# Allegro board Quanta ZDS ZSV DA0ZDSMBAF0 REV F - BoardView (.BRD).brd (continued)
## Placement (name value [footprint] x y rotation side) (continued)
R10962  10k/f_2  [R0201]  198.88 13.57 0 bottom
R10963  *100k/f_2  [R0201]  201.42 17.25 0 bottom
R10964  *1m/f_2  [R0201]  203.07 13.32 270 bottom
R10965  *0_4/s  [S0402]  119.22 36.48 180 bottom
R10966  2.2k_2  [R0201]  98.8 42.81 0 top
R10967  2.2k_2  [R0201]  98.8 43.64 0 top
R10968  4.7k_2  [R0201]  103.96 41.69 180 top
R10969  *10k/f_2  [R0201]  107.84 52.68 90 top
R10970  10k/f_2  [R0201]  102.08 37.04 0 top
R10971  2.2k_2  [R0201]  105.3 52.74 90 top
R10972  10k/f_2  [R0201]  103.37 49 180 top
R10973  *8.2k/f_2  [R0201]  99.71 38.21 270 top
R10974  *10k/f_2  [R0201]  104.77 34.17 180 top
R10975  *10k/f_2  [R0201]  99.02 34.37 0 top
R10976  *0_2  [R0201]  191.84 36.68 0 bottom
R10978  *2.2k_4  [R0402]  228.09 15.98 0 bottom
R10979  *2.2k_4  [R0402]  228.09 14.97 0 bottom
R10980  *10k/f_4  [R0402]  224.91 26.02 90 bottom
R10981  *10k/f_4  [R0402]  223.89 26.02 90 bottom
R10982  100k/f_4  [R0402]  228.09 17 180 bottom
R10983  10k/f_4  [R0402]  228.09 18.02 180 bottom
R10985  1k/f_4  [R0402]  225.93 26.02 90 bottom
R10987  10k/f_4  [R0402]  215.77 21.7 90 bottom
R10988  100k/f_4  [R0402]  215.39 19.41 270 bottom
R10989  10k/f_4  [R0402]  237.26 27.11 180 bottom
R10990  4.7k_4  [R0402]  216.4 17.13 270 bottom
R10991  10k/f_4  [R0402]  216.4 19.41 270 bottom
R10994  *7.15k/f_4  [R0402]  229.61 20.43 90 bottom
R10995  *1k/f_4  [R0402]  228.09 20.05 180 bottom
R10996  *5.9k/f_4  [R0402]  223.26 27.92 270 bottom
R10997  *2.2k_4  [R0402]  222.88 26.02 90 bottom
R10998  *0_6/s  [S0603]  228.47 25.38 0 bottom
R10999  *1m/f_2  [R0201]  188.08 5.19 0 bottom
R11000  *100k/f_2  [R0201]  196.72 3.54 270 bottom
R11001  *1m_4  [R0402]  195.95 5.95 90 bottom
R11002  *100k/f_4  [R0402]  195.95 4.17 90 bottom
R11003  *0_4/s  [S0402]  202.18 4.68 0 bottom
R11004  93.1k/f_4  [R0402]  200.65 2.9 90 bottom
R11005  100k/f_4  [R0402]  192.53 2.52 0 bottom
R11006  52.3k/f_4  [R0402]  199.64 2.9 90 bottom
R11007  10k/f_2  [R0201]  194.94 3.16 180 bottom
R11008  2m_4  [R0402]  257.42 31.1 270 bottom
R11009  10k/f_2  [R0201]  194.94 3.92 0 bottom
R11016  *100k/f_2  [R0201]  194.94 4.68 180 bottom
R11019  2m_4  [R0402]  257.42 32.87 90 bottom
R11022  *0_6/s  [S0603]  207.13 5.7 180 bottom
R11023  *0_6/s  [S0603]  207.13 7.35 180 bottom
SPAD1  *spad-re275x126np  [SPAD-RE275X126NP]  115.89 59.9 0 top
SPAD2  spad-zds-1  [SPAD-ZDS-1]  205.5 58.24 0 top
SPAD3  *spad-re275x275np  [SPAD-RE275X275NP]  25.6 58 0 top
SPAD4  *spad-c138  [SPAD-C138]  40.67 27.65 0 top
SPAD7  *spad-c138  [SPAD-C138]  24.15 18.3 0 top
SPAD8  *spad-c138  [SPAD-C138]  257.15 17.6 0 top
SPAD9  *spad-re236x118np  [SPAD-RE236X118NP]  49.37 1.51 0 top
SPAD10  *spad-re236x118np  [SPAD-RE236X118NP]  144.39 1.51 0 top
SPAD11  spad-re173x114np  [SPAD-RE173X114NP]  269.9 26.5 0 top
SPAD12  *spad-c138  [SPAD-C138]  257.15 -0.9 0 top
SPAD13  *spad-re197x197np  [SPAD-RE197X197NP]  48.3 54.19 180 bottom
SPAD14  spad-c138  [SPAD-C138]  91.17 27.65 0 top
SPAD15  spad-c138  [SPAD-C138]  57.3 18.3 0 top
SPAD16  spad-c138  [SPAD-C138]  241.67 27.65 0 top
SPAD17  spad-c138  [SPAD-C138]  191.55 27.65 0 top
SPAD18  spad-c138  [SPAD-C138]  158.05 18.3 0 top
SPAD19  spad-c138  [SPAD-C138]  208.55 17.8 0 top
SPAD20  spad-c138  [SPAD-C138]  7.55 18.3 0 top
SPAD22  spad-re236x118np  [SPAD-RE236X118NP]  201.4 1.5 0 top
SW1  t3al-23s-q-t/r  [SW-T3AL-23-Q-TR-4P]  37.9 59.5 180 bottom
SW2  *bte-p-v-t/r  [SW-BTE-P-V-TR-4P]  36.49 27.16 90 bottom
SW3  *t3al-23s-q-t/r  [SW-T3AL-23-Q-TR-4P]  60.03 3.94 180 bottom
T1  *  [TP2650]  129.66 55.73 0 top
T2  *  [TP2650]  124.58 55.23 0 top
T3  *  [TP2650]  126.51 53.32 0 top
T4  *  [TP2650]  125.85 55.02 0 top
T5  *  [TP2650]  127.02 54.49 0 top
T6  *  [TP2650]  127.78 53.45 0 top
T7  *pad  [TP2650]  111.2 53.3 0 top
T8  *  [TP2650]  101.75 52.84 0 top
T9  *  [TP2650]  122.19 53.25 0 top
T10  *  [TP2650]  126.87 55.81 0 top
T11  *  [TP2650]  118.79 52.62 0 top
T12  *  [TP2650]  120.52 52.59 0 top
T13  *  [TP2650]  128.26 55.73 0 top
T14  *  [TP2650]  128.64 54.39 0 top
T15  *  [TP2650]  131.06 51.49 0 top
T16  *  [TP2650]  104.41 51.75 0 top
T17  *  [TP2650]  103.99 50.44 0 top
T18  *  [TP2650]  40.84 49.11 180 top
T19  *pad  [TP2650]  99.71 43.72 0 top
T20  *pad  [TP2650]  58.9 46.44 0 top
T21  *pad  [TP2650]  98.29 44.38 0 top
T22  *  [TP2650]  42.13 49.11 180 top
T23  *pad  [TP2650]  98.65 41.99 0 top
T24  *pad  [TP2650]  99.33 45.23 0 top
T25  *pad  [TP2650]  100.6 42.81 0 top
T28  *pad  [TP2650]  104.44 38.14 0 top
T29  *  [TP2650]  41.24 37.99 180 top
T30  *pad  [TP2650]  100.69 37.5 0 top
T32  *  [TP2650]  100.63 35.93 0 top
T33  *  [TP2650]  80.94 35.5 90 top
T34  *pad  [TP2050]  103.91 34.78 0 top
T35  *  [TP2050]  104.51 32.54 0 top
T39  *  [TP2650]  122.83 49.87 90 bottom
T40  *  [TP2650]  126.46 49.21 270 bottom
T41  *  [TP2650]  110.08 46.92 180 bottom
T42  *pad  [TP2650]  73.53 38.08 180 bottom
T43  *  [TP2650]  111.65 37.48 180 bottom
T44  *  [TP2650]  128.85 37.37 180 bottom
T45  *  [TP2650]  109.92 36.86 180 bottom
T46  *  [TP2650]  126.33 36.72 180 bottom
T49  *  [TP2650]  111.07 36.23 180 bottom
T50  *  [TP2650]  125.37 35.62 180 bottom
T51  *  [TP2650]  117.16 35.24 180 bottom
T52  *  [TP2650]  111.19 34.93 180 bottom
T53  *  [TP2650]  128.34 34.78 180 bottom
T54  *  [TP2650]  109.34 34.61 180 bottom
T56  *pad  [TP2650]  60.12 18.74 180 bottom
T60  *pad  [TP2650]  58.79 10.35 180 bottom
T62  *pad  [TP2050]  167 15.73 90 bottom
T63  *pad  [TP2050]  167.74 13.49 90 bottom
T64  *pad  [TP2050]  156.05 6.08 90 bottom
T65  *pad  [TP2050]  156.56 4.88 90 bottom
T68  *pad  [TP2650]  151.02 2.38 90 bottom
T69  *pad  [TP2650]  152.29 2.38 90 bottom
T70  *pad  [TP2050]  153.56 2.38 90 bottom
TP3  *  [TP2650]  244.19 11.59 0 bottom
TP6  *pad_nc  [TP2050]  226.56 23.98 180 bottom
TP23  *pad_nc  [TP2050]  218.1 19.57 180 bottom
TP24  *pad_nc  [TP2050]  218.56 23.6 180 bottom
TP25  *pad_nc  [TP2050]  218.43 16.62 180 bottom
TP26  *pad_nc  [TP2050]  222.62 15.98 180 bottom
TP27  *pad_nc  [TP2050]  230.04 23.1 180 bottom
TP28  *pad_nc  [TP2050]  222.88 13.29 180 bottom
TP29  *pad_nc  [TP2050]  223.79 15.48 180 bottom
TP30  *pad_nc  [TP2050]  223.77 14.21 180 bottom
TP31  *pad_nc  [TP2050]  226.64 16.11 180 bottom
TP32  *pad_nc  [TP2050]  226.64 14.71 180 bottom
TP38  *pad_nc  [TP2050]  229.61 17.76 180 bottom
TP39  *pad_nc  [TP2050]  230.24 19.03 180 bottom
TP88  *  [TP2050]  171.7 4.81 180 bottom
TP89  *  [TP2050]  171.67 8.08 180 bottom
U1  gd25b64csigr  [SOIC8-8-1_27]  45.63 46.28 90 top
U2  tc7sh08fu(f)  [SSOP5-P-A-TOSHIBA-B]  99.26 51.07 180 top
U3  skylake_ulx/bga  [BGA1515-INTEL-SKL_KBL-Y]  117.6 41.85 270 top
U4  mll@az1045-08f.r7g  [ESD-3_8X1-9P]  260.8 30.46 90 top
U4A1  lpddr3_ss_8gl  [BGA178-SAMSUNG-K4E8E304EE]  106.27 18.49 180 bottom
U5  14@lis3dhtr  [LGA16-3X3-5]  84.4 34.79 90 top
U5A1  lpddr3_ss_8gl  [BGA178-SAMSUNG-K4E8E304EE]  124.04 18.49 180 bottom
U6A1  lpddr3_ss_8gl  [BGA178-SAMSUNG-K4E8E304EE]  147 19.63 270 bottom
U7A1  lpddr3_ss_8gl  [BGA178-SAMSUNG-K4E8E304EE]  147 36.96 270 bottom
U8  mll@az1043-08f.r7g  [ESD-3_8X1-9P]  259.45 34.27 90 bottom
U9  tmp432adgsr  [TSSOP10-4_9-5]  85.65 27.08 90 bottom
U10  tps2592badrcr  [QFN10-3X3-5-16P]  199.64 21.19 180 bottom
U11  *tc7sh08fu(f)  [SSOP5-P-A-TOSHIBA-B]  200.4 15.35 180 bottom
U13  ps8743bqfn40gtr-b0  [QFN40-6X4-4-41P-0_8H]  251.38 22.9 180 bottom
U14  ptn36001  [QFN12-1_25X2_1-4]  233.8 24.87 270 bottom
U15  cbtl02043abq  [DHVQFN20-4_5X2_5-5-21P]  240.28 24.37 90 bottom
U16  ap21510fm-7  [DFN2018-6-1_8125X2_0125-5-7P]  220.97 14.46 270 bottom
U17  it8987vg/bx  [BGA128-ITE-IT8528VGAX]  51.89 10.91 270 bottom
U18  ap21510fm-7  [DFN2018-6-1_8125X2_0125-5-7P]  220.08 25.66 180 bottom
U19  alc255-cg  [QFN48-6X6-4-49P-ALC280]  247.95 8.47 0 bottom
U20  14@it8350g-128/cx-002c  [BGA64-ITE-IT8562VGCX]  152.06 6.29 90 bottom
U21  *g923-330t1uf  [SOT23-5]  236.65 3.72 180 bottom
U39  **poa@pi3usb102  [TQFN10-1_6X1_3-4-SMT]  172.84 6.43 180 bottom
U40  cypd4225-40lqxit  [QFN40-6X6-5-41P-0_6H]  222.37 20.3 180 bottom
U41  mll@az1043-08f.r7g  [ESD-3_8X1-9P]  259.84 28.56 270 bottom
U42  mll@az1045-08f.r7g  [ESD-3_8X1-9P]  261.87 30.84 90 bottom
U43  tps2592badrcr  [QFN10-3X3-5-16P]  198.88 6.2 90 bottom
U44  *tc7sh08fu(f)  [SSOP5-P-A-TOSHIBA-B]  193.03 4.68 90 bottom
Y1  24mhz_30  [XTL-3_2X2_5-2_2X1_7-0_8H]  99.69 48.09 0 top
Y2  32.768khz_20  [XTL-3_2X1_5-2_5-0_8H]  101.29 32.96 90 top

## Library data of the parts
BAT1 = 50277-01001-V01-10P-L
C1-C4 C12 C13 C44 C58 C69 C70 C73 C74 C77-C79 C82 C84 C85 C87-C89 C92-C95 C97-C110 C112 C113 C115-C120 C122-C129 C131-C133 C135-C144 C146-C148 C150-C159 C162-C174 C177-C184 C186 C188-C193 C195-C198 C200-C207 C210 C211 C213-C219 C221-C224 C226 C227 C229-C232 C234 C236-C246 C248-C258 C260 C261 C264 C266 C269-C276 C278 C279 C281 C283 C291 C310 C311 C324 C326 C330-C332 C334 C335 C352 C354 C356 C357 C374 C380 C388-C411 C413 C415-C417 C423 C424 C438 C440 C455 C456 C458 C461 C463 C464 C703 EC1-EC11 PC1-PC4 PC20 PC24 PC26-PC29 PC35 PC36 PC41 PC47 PC49-PC51 PC53 PC55 PC58-PC61 PC63 PC79 PC82-PC85 PC89-PC91 PC96-PC99 PC101 PC108 PC116-PC119 PC122 PC126 PC134-PC137 PC139 PC140 PC142-PC144 PC147 PC148 PC150 PC153 PC157 PC158 PC166 PC170 PC172 PC173 PC176 PC179 PC181-PC183 PC186 PC187 PC191 PC195-PC199 PC202 PC204 PC206 PC209 PC210 PC220 PC229 PC245 PC248-PC251 = C0201
C4A1-C4A5 C5 C5L1-C5L5 C6 C6A1-C6A9 C6L1-C6L9 C7 C7A1 C7A2 C7L1-C7L16 C9-C11 C14 C15 C19-C32 C41-C43 C45-C55 C57 C59-C68 C72 C75 C76 C86 C90 C91 C111 C114 C121 C130 C134 C145 C149 C160 C161 C175 C176 C185 C187 C194 C199 C209 C212 C225 C233 C235 C247 C259 C262 C263 C265 C267 C268 C277 C280 C282 C284-C290 C292-C305 C307-C309 C313-C318 C322 C323 C325 C327-C329 C333 C336-C351 C353 C355 C358 C359 C362 C364 C365 C367-C373 C375-C379 C381-C387 C412 C414 C418-C421 C428-C434 C436 C437 C439 C441-C447 C451-C454 C457 C459 C460 C462 C466-C468 C470-C473 C477-C482 C725 C726 C731 C927-C931 C941-C961 D1 D6-D13 D23 D28 D31 D49 D50 PC6 PC16 PC25 PC38-PC40 PC43 PC44 PC46 PC48 PC54 PC57 PC62 PC64 PC65 PC70 PC80 PC81 PC86-PC88 PC92-PC95 PC100 PC102 PC105-PC107 PC110-PC112 PC115 PC120 PC121 PC128 PC133 PC141 PC145 PC146 PC149 PC151 PC152 PC154-PC156 PC160-PC165 PC169 PC174 PC175 PC177 PC178 PC180 PC185 PC188 PC190 PC193 PC194 PC200 PC201 PC203 PC205 PC207 PC211 PC214 PC215 PC218 PC222 PC223 PC226-PC228 PC231-PC233 PC235 PC237-PC239 PC241-PC244 = C0402
C16-C18 C71 C80 C81 C83 C96 C228 C483-C491 C933 C962-C964 = C0805
C306 C312 C360 C425 C426 C934-C940 C965 PC5 PC7-PC15 PC17-PC19 PC21-PC23 PC30-PC34 PC37 PC42 PC45 PC52 PC56 PC66-PC69 PC71-PC78 PC109 PC113 PC114 PC123-PC125 PC127 PC129-PC132 PC138 PC159 PC167 PC168 PC171 PC184 PC189 PC192 PC208 PC212 PC213 PC216 PC217 PC219 PC221 PC224 PC225 PC230 PC234 PC236 PC240 PC255 PC256 = C0603
CL1_CL1 CL1_CL2 = FUNTP-C50-79-2P
CN1 = NGFF-NASE0-A6701-1S14-75P-KE
CN2 = NGFF-80149-3521-75P-KB
CN3 CN18 = UB31-DX07B024XJ1AR1000-24P-SMT
CN5 = AUDIO-AJ3F7D-Y150-412-6P
CN6 CN7 = 50376-00801-V01-8P-L
CN8 = 4251K-F06N-00L-6P-L
CN9 = 51569-03201-001-32P-L
CN10 = 50521-0060N-V01-6P-L
CN11 = 50699-02601-AT1-26P-L
CN12 = 50521-00641-V01-6P-L
CN13 CN14 = 50277-00201-001-2P-L
CN16 CN17 = 50521-00801-V01-8P-L
D2 L12 PR46 PR59 PR66 PR69 PR82 PR100 PR106 PR137 PR139 PR141 PR144 PR154 PR163 PR164 PR180-PR183 PR218 PR310 PR497 R284 R298 R311 R370 R380 R485 = R0603
D3 D18-D22 D35 D36 D39 PD3 PD6 PD7 = DSM
D4 D51 = D-1X0_6-D24V0L1B2LPS
D14-D17 EL1 L11 L14 L15 PR20 PR21 PR24 PR28 PR31 PR41 PR53 PR56 PR184-PR189 PR193 PR201 PR208 PR212 PR213 PR215 PR221 PR223 PR232 PR237 PR241 PR247 PR249 PR254 PR255 PR266 PR270 PR273 PR279 PR282-PR284 PR293 PR300 PR305-PR307 PR309 PR312-PR315 PR325 PR507 R4 R4L1 R4L2 R5L1 R5L2 R6L1-R6L3 R7A1 R39 R49 R53 R63 R81 R88 R89 R95 R115 R131 R139-R141 R149-R155 R157 R158 R170 R196-R198 R211 R219 R229 R249-R251 R254 R264 R274-R276 R282 R292 R299 R300 R308 R309 R313 R323 R325 R329 R341 R346 R351 R363-R365 R371 R372 R374 R378 R387 R389 R395-R397 R418 R425 R433 R434 R439 R444 R450 R472 R475 R477 R479 R481 R486 R490 R492-R497 R504 R675 R676 R10941 R10957 R10978-R10983 R10985 R10987-R10991 R10994-R10997 R11001 R11002 R11004-R11006 R11008 R11019 = R0402
D24-D27 D29 D30 D32-D34 D37 D38 = ESD-69X31
HOLE1 = H-TC276BC236D197P2
HOLE2 = H-TC315BC236D197P2
HOLE3 = H-C197D98P2BB
HOLE4 = H-O79X118D79X118N
HOLE5 HOLE9 = H-TC256BC177D177P2
HOLE6 = H-C79D79N
HOLE7 HOLE8 HOLE11 = H-TC217IBC197D98P2BB
HOLE10 = H-T99I-2BB
HOLE12 = H-T99I-1
HOLE13 HOLE14 = H-C51D51N
L13 PR280 = R0805
LED1-LED4 = LEDLTST-C190TGKT
LED5 LED6 = LEDLTST-S326KGJRKT-3P-SMT
MR1 = SOT23_123-2_8-1_9
PC103 PC104 = CC7343
PD1 = D-5_8X4_3-3P
PD2 PD4 PD9-PD13 = D-SOD523-1_2X0_8-1N4148WT-7
PD5 = D-DO-214AC
PL1 PL9 PL14 = CHOKE-PCMB041B-1R0MS
PL2 = L6_6X6_47-1_3
PL3 = L4_2X4_2
PL4 PL11 PL12 PL15 PR3 PR7 PR177 R226 R231 = S0805
PL5 = CHOKE-PCMB053T-1R0MS
PL6 PL7 = CHOKE-MPL73-1R5
PL8 PL10 PL13 = L3_2X2_5-1_55
PQ1-PQ5 PQ10 = POWER-3X3-65-10P
PQ6 PQ7 = POWER-5X6-1_27-7P
PQ8 PQ16 PQ19 PQ24 PQ27 PQ28 Q1-Q4 Q8 Q12-Q15 Q17 Q20-Q22 Q24 Q25 Q27-Q29 Q31 Q34 Q6062 Q6063 Q6068 Q6069 Q6071 = SOT23_213-3_3-2
PQ9 PQ23 PQ26 = SOT363-2_1-65-6P
PQ11 PQ12 PQ14 PQ17 PQ20 PQ21 = WDFN5-3_05X3_05-65
PQ15 PQ22 Q10 Q11 Q16 Q18 Q26 Q33 Q48 Q6064 Q6066 Q6067 Q6072 = SC70-2_1-65-6P
PR1 PR6 PR8 PR9 PR23 PR27 PR48 PR50-PR52 PR55 PR58 PR171 PR176 PR178 PR179 PR219 PR246 PR271 PR524 PR526 R171 R285 R296 R297 R310 R350 R355 R381 R393 R410 R417 R484 R10998 R11022 R11023 = S0603
PR2 PR4 PR5 PR12-PR19 PR33-PR38 PR43-PR45 PR47 PR54 PR57 PR60-PR63 PR65 PR70 PR71 PR73 PR75-PR77 PR86 PR87 PR89-PR91 PR93-PR98 PR102 PR103 PR109 PR110 PR113 PR114 PR116 PR123 PR126 PR127 PR132 PR134-PR136 PR138 PR143 PR146 PR147 PR149 PR151 PR155 PR161 PR166 PR168-PR170 PR172-PR174 PR190-PR192 PR198 PR203 PR210 PR222 PR224 PR230 PR231 PR234 PR239 PR244 PR250 PR258 PR259 PR261 PR262 PR264 PR285-PR287 PR290 PR291 PR294 PR298 PR299 PR301 PR302 PR304 PR308 PR330 PR492 PR493 PR502 PR525 R1 R5 R10 R16 R17 R31 R42 R43 R47 R96 R101 R106 R111 R116 R118 R120 R123 R142 R162 R165 R201 R207 R209 R212 R213 R224 R227 R255 R256 R259 R260 R295 R327 R335 R354 R382 R383 R404 R405 R408 R436 R441 R451 R460 R467 R487 R502 R505 R10946 R10947 R10960 = S0201
PR10 PR11 PR22 PR26 PR30 PR32 PR39 PR40 PR42 PR49 PR64 PR67 PR68 PR72 PR74 PR78-PR81 PR84 PR85 PR88 PR92 PR99 PR101 PR104 PR105 PR107 PR108 PR111 PR112 PR115 PR117-PR122 PR124 PR125 PR128-PR131 PR133 PR140 PR142 PR148 PR150 PR152 PR153 PR156-PR160 PR162 PR165 PR167 PR175 PR194 PR195 PR197 PR199 PR200 PR202 PR204-PR207 PR209 PR214 PR216 PR217 PR220 PR225-PR229 PR233 PR236 PR238 PR240 PR243 PR245 PR248 PR251-PR253 PR257 PR263 PR265 PR267-PR269 PR272 PR274-PR278 PR281 PR288 PR292 PR295-PR297 PR303 PR316-PR321 PR324 PR326 PR328 PR331 PR332 PR334 PR335 PR337 PR340-PR342 PR491 PR494-PR496 PR498-PR501 PR503-PR506 PR508-PR510 PR512-PR514 PR516-PR521 PR523 R2 R6-R9 R11-R15 R18-R30 R32-R38 R40 R41 R45 R46 R48 R50-R52 R54-R62 R64-R71 R73-R78 R80 R82-R84 R86 R87 R90-R94 R97-R100 R102 R103 R105 R107-R110 R112-R114 R117 R119 R121 R122 R124-R130 R133 R135 R136 R143 R144 R156 R161 R163 R164 R166-R169 R172-R180 R183 R184 R186-R195 R199 R200 R202-R206 R208 R214 R216-R218 R222 R223 R228 R230 R232 R236 R238 R241-R245 R247 R252 R253 R257 R258 R262 R263 R265 R266 R269 R273 R279-R281 R290 R291 R301-R306 R314 R318-R321 R324 R326 R330-R334 R336-R339 R342 R344 R345 R347 R352 R353 R356-R362 R366-R368 R373 R377 R384 R386 R390 R391 R399 R409 R411-R414 R416 R420-R422 R426 R427 R429 R430 R432 R435 R442 R443 R445-R447 R452 R455-R457 R459 R461 R462 R466 R473 R478 R482 R483 R488 R489 R499-R501 R503 R514 R543 R659 R668 R677 R860 R1526-R1534 R10930-R10932 R10934 R10942-R10944 R10948-R10956 R10959 R10961-R10964 R10966-R10976 R10999 R11000 R11007 R11009 R11016 = R0201
PR25 PR29 PR83 PR145 PR196 PR211 PR235 PR242 PR256 PR311 PR327 PR515 PR522 R3 R104 R145 R146 R160 R220 R240 R283 R307 R379 R392 R402 R423 R448 R474 R10965 R11003 = S0402
PR260 PR289 = F3_2X1_65-2_8
PU1 PU3 PU6 PU9 PU13 PU22 = SON14-3X2-4-15P-SMT
PU2 = DFN8-2X2-5-9P-NCP5901
PU4 = SOT23-5-2_8-95-5P-G708
PU5 = BGA168-TEXAS-TPS650830ZAJT
PU7 PU11 = QFN13-2X3-5
PU8 PU10 PU18-PU20 = SOT353-1-2_125-65-5P
PU12 = QFN52-6X6-4-53P-1H
PU14 = QFN28-4X4-4-38P
PU15 = TDFN10-3X3-5-11P-APL5620QBI-TRG
PU16 PU17 PU21 = SOT23-5-2_8-95-5P-1_3H
Q19 Q6070 = PG-TSDSON-8-8P-R
Q23 Q30 = UMT_213-3-1_3
SPAD1 = SPAD-RE275X126NP
SPAD2 = SPAD-ZDS-1
SPAD3 = SPAD-RE275X275NP
SPAD4 SPAD7 SPAD8 SPAD12 SPAD14-SPAD20 = SPAD-C138
SPAD9 SPAD10 SPAD22 = SPAD-RE236X118NP
SPAD11 = SPAD-RE173X114NP
SPAD13 = SPAD-RE197X197NP
SW1 SW3 = SW-T3AL-23-Q-TR-4P
SW2 = SW-BTE-P-V-TR-4P
T1-T25 T28-T30 T32 T33 T39-T46 T49-T54 T56 T60 T68 T69 TP3 = TP2650
T34 T35 T62-T65 T70 TP6 TP23-TP32 TP38 TP39 TP88 TP89 = TP2050
U1 = SOIC8-8-1_27
U2 U11 U44 = SSOP5-P-A-TOSHIBA-B
U3 = BGA1515-INTEL-SKL_KBL-Y
U4 U8 U41 U42 = ESD-3_8X1-9P
U4A1 U5A1 U6A1 U7A1 = BGA178-SAMSUNG-K4E8E304EE
U5 = LGA16-3X3-5
U9 = TSSOP10-4_9-5
U10 U43 = QFN10-3X3-5-16P
U13 = QFN40-6X4-4-41P-0_8H
U14 = QFN12-1_25X2_1-4
U15 = DHVQFN20-4_5X2_5-5-21P
U16 U18 = DFN2018-6-1_8125X2_0125-5-7P
U17 = BGA128-ITE-IT8528VGAX
U19 = QFN48-6X6-4-49P-ALC280
U20 = BGA64-ITE-IT8562VGCX
U21 = SOT23-5
U39 = TQFN10-1_6X1_3-4-SMT
U40 = QFN40-6X6-5-41P-0_6H
Y1 = XTL-3_2X2_5-2_2X1_7-0_8H
Y2 = XTL-3_2X1_5-2_5-0_8H

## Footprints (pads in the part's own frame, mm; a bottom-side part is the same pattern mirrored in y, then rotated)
4251K-F06N-00L-6P-L
  rect 0.406x0.61 smd: 1(-1.5,1.375) 2(-0.9,1.375) 3(-0.3,1.375) 4(0.3,1.375) 5(0.9,1.375) 6(1.5,1.375)
  rect 0.711x1.041 smd: 7(-2.45,0) 8(2.45,0)
50277-00201-001-2P-L
  rect 0.787x1.905 smd: 1(-0.625,4.925) 2(0.625,4.925)
  rect 1.295x3.353 smd: 3(-3.475,0) 4(3.475,0)
50277-01001-V01-10P-L
  rect 0.787x1.905 smd: 1(-5.625,4.925) 2(-4.375,4.925) 3(-3.125,4.925) 4(-1.875,4.925) 5(-0.625,4.925) 6(0.625,4.925) 7(1.875,4.925) 8(3.125,4.925) 9(4.375,4.925) 10(5.625,4.925)
  rect 1.295x3.353 smd: 11(-8.475,0) 12(8.475,0)
50376-00801-V01-8P-L
  rect 0.406x0.61 smd: 1(-2.1,1.375) 2(-1.5,1.375) 3(-0.9,1.375) 4(-0.3,1.375) 5(0.3,1.375) 6(0.9,1.375) 7(1.5,1.375) 8(2.1,1.375)
  rect 0.711x1.041 smd: 9(-3.05,0) 10(3.05,0)
50521-0060N-V01-6P-L
  rect 0.305x0.787 smd: 1(-1.25,2.5) 2(-0.75,2.5) 3(-0.25,2.5) 4(0.25,2.5) 5(0.75,2.5) 6(1.25,2.5)
  rect 0.406x0.787 smd: 7(-2.25,0) 8(2.25,0)
50521-00641-V01-6P-L
  rect 0.305x0.787 smd: 1(-1.25,2.5) 2(-0.75,2.5) 3(-0.25,2.5) 4(0.25,2.5) 5(0.75,2.5) 6(1.25,2.5)
  rect 0.406x0.787 smd: 7(-2.25,0) 8(2.25,0)
50521-00801-V01-8P-L
  rect 0.305x0.787 smd: 1(-1.75,2.5) 2(-1.25,2.5) 3(-0.75,2.5) 4(-0.25,2.5) 5(0.25,2.5) 6(0.75,2.5) 7(1.25,2.5) 8(1.75,2.5)
  rect 0.406x0.787 smd: 9(-2.75,0) 10(2.75,0)
50699-02601-AT1-26P-L
  rect 0.229x0.787 smd: 1(-10,3.3) 2(-9.2,3.3) 3(-8.4,3.3) 4(-7.6,3.3) 5(-6.8,3.3) 6(-6,3.3) 7(-5.2,3.3) 8(-4.4,3.3) 9(-3.6,3.3) 10(-2.8,3.3) 11(-2,3.3) 12(-1.2,3.3) 13(-0.4,3.3) 14(0.4,3.3) 15(1.2,3.3) 16(2,3.3) 17(2.8,3.3) 18(3.6,3.3) 19(4.4,3.3) 20(5.2,3.3) 21(6,3.3) 22(6.8,3.3) 23(7.6,3.3) 24(8.4,3.3) 25(9.2,3.3) 26(10,3.3)
  rect 0.559x1.295 smd: 27(-11.625,0) 28(11.625,0)
51569-03201-001-32P-L
  round 0.787 hole 0.787 unplated: (-8.8,0) (8.8,0)
  rect 0.305x0.889 smd: 1(-7.75,3.85) 2(-7.25,3.85) 3(-6.75,3.85) 4(-6.25,3.85) 5(-5.75,3.85) 6(-5.25,3.85) 7(-4.75,3.85) 8(-4.25,3.85) 9(-3.75,3.85) 10(-3.25,3.85) 11(-2.75,3.85) 12(-2.25,3.85) 13(-1.75,3.85) 14(-1.25,3.85) 15(-0.75,3.85) 16(-0.25,3.85) 17(0.25,3.85) 18(0.75,3.85) 19(1.25,3.85) 20(1.75,3.85) 21(2.25,3.85) 22(2.75,3.85) 23(3.25,3.85) 24(3.75,3.85) 25(4.25,3.85) 26(4.75,3.85) 27(5.25,3.85) 28(5.75,3.85) 29(6.25,3.85) 30(6.75,3.85) 31(7.25,3.85) 32(7.75,3.85)
  rect 1.499x1.499 smd: 33(-10.25,-0.3) 34(10.25,-0.3)
AUDIO-AJ3F7D-Y150-412-6P
  rect 1.245x2.007 hole 0.508x1.397: 1(-4.35,-3) 2(-4.35,0.05) 3(-4.35,5.7) 4(4.35,5.7) 5(4.35,0.05) 6(4.35,-3)
BGA64-ITE-IT8562VGCX
  round 0.254 smd: A1(-2,2) A2(-1.5,2) A3(-1,2) A4(-0.5,2) A5(0,2) A6(0.5,2) A7(1,2) A8(1.5,2) A9(2,2) B1(-2,1.5) B9(2,1.5) C1(-2,1) C9(2,1) D1(-2,0.5) D9(2,0.5) E1(-2,0) E9(2,0) F1(-2,-0.5) F9(2,-0.5) G1(-2,-1) G9(2,-1) H1(-2,-1.5) H9(2,-1.5) J1(-2,-2) J2(-1.5,-2) J3(-1,-2) J4(-0.5,-2) J5(0,-2) J6(0.5,-2) J7(1,-2) J8(1.5,-2) J9(2,-2)
  round 0.279 smd: B2(-1.5,1.5) B3(-1,1.5) B4(-0.5,1.5) B5(0,1.5) B6(0.5,1.5) B7(1,1.5) B8(1.5,1.5) C2(-1.5,1) C8(1.5,1) D2(-1.5,0.5) D4(-0.5,0.5) D5(0,0.5) D6(0.5,0.5) D8(1.5,0.5) E2(-1.5,0) E4(-0.5,0) E6(0.5,0) E8(1.5,0) F2(-1.5,-0.5) F4(-0.5,-0.5) F5(0,-0.5) F6(0.5,-0.5) F8(1.5,-0.5) G2(-1.5,-1) G8(1.5,-1) H2(-1.5,-1.5) H3(-1,-1.5) H4(-0.5,-1.5) H5(0,-1.5) H6(0.5,-1.5) H7(1,-1.5) H8(1.5,-1.5)
BGA128-ITE-IT8528VGAX
  round 0.254 smd: A1(-3,-3) A2(-3,-2.5) A3(-3,-2) A4(-3,-1.5) A5(-3,-1) A6(-3,-0.5) A7(-3,0) A8(-3,0.5) A9(-3,1) A10(-3,1.5) A11(-3,2) A12(-3,2.5) A13(-3,3) B1(-2.5,-3) B2(-2.5,-2.5) B3(-2.5,-2) B4(-2.5,-1.5) B5(-2.5,-1) B6(-2.5,-0.5) B7(-2.5,0) B8(-2.5,0.5) B9(-2.5,1) B10(-2.5,1.5) B11(-2.5,2) B12(-2.5,2.5) B13(-2.5,3) C1(-2,-3) C2(-2,-2.5) C12(-2,2.5) C13(-2,3) D1(-1.5,-3) D2(-1.5,-2.5) D4(-1.5,-1.5) D5(-1.5,-1) D6(-1.5,-0.5) D7(-1.5,0) D8(-1.5,0.5) D9(-1.5,1) D10(-1.5,1.5) D12(-1.5,2.5) D13(-1.5,3) E1(-1,-3) E2(-1,-2.5) E4(-1,-1.5) E5(-1,-1) E6(-1,-0.5) E7(-1,0) E8(-1,0.5) E9(-1,1) E10(-1,1.5) E12(-1,2.5) E13(-1,3) F1(-0.5,-3) F2(-0.5,-2.5) F4(-0.5,-1.5) F5(-0.5,-1) F9(-0.5,1) F10(-0.5,1.5) F12(-0.5,2.5) F13(-0.5,3) G1(0,-3) G2(0,-2.5) G4(0,-1.5) G5(0,-1) G9(0,1) G10(0,1.5) G12(0,2.5) G13(0,3) H1(0.5,-3) H2(0.5,-2.5) H4(0.5,-1.5) H5(0.5,-1) H9(0.5,1) H10(0.5,1.5) H12(0.5,2.5) H13(0.5,3) J1(1,-3) J2(1,-2.5) J4(1,-1.5) J5(1,-1) J6(1,-0.5) J7(1,0) J8(1,0.5) J9(1,1) J10(1,1.5) J12(1,2.5) J13(1,3) K1(1.5,-3) K2(1.5,-2.5) K4(1.5,-1.5) K5(1.5,-1) K6(1.5,-0.5) K7(1.5,0) K8(1.5,0.5) K9(1.5,1) K10(1.5,1.5) K12(1.5,2.5) K13(1.5,3) L1(2,-3) L2(2,-2.5) L12(2,2.5) L13(2,3) M1(2.5,-3) M2(2.5,-2.5) M3(2.5,-2) M4(2.5,-1.5) M5(2.5,-1) M6(2.5,-0.5) M7(2.5,0) M8(2.5,0.5) M9(2.5,1) M10(2.5,1.5) M11(2.5,2) M12(2.5,2.5) M13(2.5,3) N1(3,-3) N2(3,-2.5) N3(3,-2) N4(3,-1.5) N5(3,-1) N6(3,-0.5) N7(3,0) N8(3,0.5) N9(3,1) N10(3,1.5) N11(3,2) N12(3,2.5) N13(3,3)
BGA168-TEXAS-TPS650830ZAJT
  round 0.254 smd: A1(-3,-3) A2(-3,-2.5) A3(-3,-2) A4(-3,-1.5) A5(-3,-1) A6(-3,-0.5) A7(-3,0) A8(-3,0.5) A9(-3,1) A10(-3,1.5) A11(-3,2) A12(-3,2.5) A13(-3,3) B1(-2.5,-3) B3(-2.5,-2) B4(-2.5,-1.5) B5(-2.5,-1) B6(-2.5,-0.5) B7(-2.5,0) B8(-2.5,0.5) B9(-2.5,1) B10(-2.5,1.5) B11(-2.5,2) B12(-2.5,2.5) B13(-2.5,3) C1(-2,-3) C2(-2,-2.5) C3(-2,-2) C4(-2,-1.5) C5(-2,-1) C6(-2,-0.5) C7(-2,0) C8(-2,0.5) C9(-2,1) C10(-2,1.5) C11(-2,2) C12(-2,2.5) C13(-2,3) D1(-1.5,-3) D2(-1.5,-2.5) D3(-1.5,-2) D4(-1.5,-1.5) D5(-1.5,-1) D6(-1.5,-0.5) D7(-1.5,0) D8(-1.5,0.5) D9(-1.5,1) D10(-1.5,1.5) D11(-1.5,2) D12(-1.5,2.5) D13(-1.5,3) E1(-1,-3) E2(-1,-2.5) E3(-1,-2) E4(-1,-1.5) E5(-1,-1) E6(-1,-0.5) E7(-1,0) E8(-1,0.5) E9(-1,1) E10(-1,1.5) E11(-1,2) E12(-1,2.5) E13(-1,3) F1(-0.5,-3) F2(-0.5,-2.5) F3(-0.5,-2) F4(-0.5,-1.5) F5(-0.5,-1) F6(-0.5,-0.5) F7(-0.5,0) F8(-0.5,0.5) F9(-0.5,1) F10(-0.5,1.5) F11(-0.5,2) F12(-0.5,2.5) F13(-0.5,3) G1(0,-3) G2(0,-2.5) G3(0,-2) G4(0,-1.5) G5(0,-1) G6(0,-0.5) G7(0,0) G8(0,0.5) G9(0,1) G10(0,1.5) G11(0,2) G12(0,2.5) G13(0,3) H1(0.5,-3) H2(0.5,-2.5) H3(0.5,-2) H4(0.5,-1.5) H5(0.5,-1) H6(0.5,-0.5) H7(0.5,0) H8(0.5,0.5) H9(0.5,1) H10(0.5,1.5) H11(0.5,2) H12(0.5,2.5) H13(0.5,3) J1(1,-3) J2(1,-2.5) J3(1,-2) J4(1,-1.5) J5(1,-1) J6(1,-0.5) J7(1,0) J8(1,0.5) J9(1,1) J10(1,1.5) J11(1,2) J12(1,2.5) J13(1,3) K1(1.5,-3) K2(1.5,-2.5) K3(1.5,-2) K4(1.5,-1.5) K5(1.5,-1) K6(1.5,-0.5) K7(1.5,0) K8(1.5,0.5) K9(1.5,1) K10(1.5,1.5) K11(1.5,2) K12(1.5,2.5) K13(1.5,3) L1(2,-3) L2(2,-2.5) L3(2,-2) L4(2,-1.5) L5(2,-1) L6(2,-0.5) L7(2,0) L8(2,0.5) L9(2,1) L10(2,1.5) L11(2,2) L12(2,2.5) L13(2,3) M1(2.5,-3) M2(2.5,-2.5) M3(2.5,-2) M4(2.5,-1.5) M5(2.5,-1) M6(2.5,-0.5) M7(2.5,0) M8(2.5,0.5) M9(2.5,1) M10(2.5,1.5) M11(2.5,2) M12(2.5,2.5) M13(2.5,3) N1(3,-3) N2(3,-2.5) N3(3,-2) N4(3,-1.5) N5(3,-1) N6(3,-0.5) N7(3,0) N8(3,0.5) N9(3,1) N10(3,1.5) N11(3,2) N12(3,2.5) N13(3,3)
BGA178-SAMSUNG-K4E8E304EE
  round 0.254 smd: A1(-5.2,-4.8) A2(-5.2,-4) A3(-5.2,-3.2) A4(-5.2,-2.4) A5(-5.2,-1.6) A6(-5.2,-0.8) A8(-5.2,0.8) A9(-5.2,1.6) A10(-5.2,2.4) A11(-5.2,3.2) A12(-5.2,4) A13(-5.2,4.8) B1(-4.55,-4.8) B2(-4.55,-4) B3(-4.55,-3.2) B4(-4.55,-2.4) B5(-4.55,-1.6) B6(-4.55,-0.8) B8(-4.55,0.8) B9(-4.55,1.6) B10(-4.55,2.4) B11(-4.55,3.2) B12(-4.55,4) B13(-4.55,4.8) C2(-3.9,-4) C3(-3.9,-3.2) C4(-3.9,-2.4) C5(-3.9,-1.6) C6(-3.9,-0.8) C8(-3.9,0.8) C9(-3.9,1.6) C10(-3.9,2.4) C11(-3.9,3.2) C12(-3.9,4) D2(-3.25,-4) D3(-3.25,-3.2) D4(-3.25,-2.4) D5(-3.25,-1.6) D6(-3.25,-0.8) D8(-3.25,0.8) D9(-3.25,1.6) D10(-3.25,2.4) D11(-3.25,3.2) D12(-3.25,4) E2(-2.6,-4) E3(-2.6,-3.2) E4(-2.6,-2.4) E5(-2.6,-1.6) E6(-2.6,-0.8) E8(-2.6,0.8) E9(-2.6,1.6) E10(-2.6,2.4) E11(-2.6,3.2) E12(-2.6,4) F2(-1.95,-4) F3(-1.95,-3.2) F4(-1.95,-2.4) F5(-1.95,-1.6) F6(-1.95,-0.8) F8(-1.95,0.8) F9(-1.95,1.6) F10(-1.95,2.4) F11(-1.95,3.2) F12(-1.95,4) G2(-1.3,-4) G3(-1.3,-3.2) G4(-1.3,-2.4) G5(-1.3,-1.6) G6(-1.3,-0.8) G8(-1.3,0.8) G9(-1.3,1.6) G10(-1.3,2.4) G11(-1.3,3.2) G12(-1.3,4) H2(-0.65,-4) H3(-0.65,-3.2) H4(-0.65,-2.4) H5(-0.65,-1.6) H6(-0.65,-0.8) H8(-0.65,0.8) H9(-0.65,1.6) H10(-0.65,2.4) H11(-0.65,3.2) H12(-0.65,4) J2(0,-4) J3(0,-3.2) J4(0,-2.4) J5(0,-1.6) J6(0,-0.8) J8(0,0.8) J9(0,1.6) J10(0,2.4) J11(0,3.2) J12(0,4) K2(0.65,-4) K3(0.65,-3.2) K4(0.65,-2.4) K5(0.65,-1.6) K6(0.65,-0.8) K8(0.65,0.8) K9(0.65,1.6) K10(0.65,2.4) K11(0.65,3.2) K12(0.65,4) L2(1.3,-4) L3(1.3,-3.2) L4(1.3,-2.4) L5(1.3,-1.6) L6(1.3,-0.8) L8(1.3,0.8) L9(1.3,1.6) L10(1.3,2.4) L11(1.3,3.2) L12(1.3,4) M2(1.95,-4) M3(1.95,-3.2) M4(1.95,-2.4) M5(1.95,-1.6) M6(1.95,-0.8) M8(1.95,0.8) M9(1.95,1.6) M10(1.95,2.4) M11(1.95,3.2) M12(1.95,4) N2(2.6,-4) N3(2.6,-3.2) N4(2.6,-2.4) N5(2.6,-1.6) N6(2.6,-0.8) N8(2.6,0.8) N9(2.6,1.6) N10(2.6,2.4) N11(2.6,3.2) N12(2.6,4) P2(3.25,-4) P3(3.25,-3.2) P4(3.25,-2.4) P5(3.25,-1.6) P6(3.25,-0.8) P8(3.25,0.8) P9(3.25,1.6) P10(3.25,2.4) P11(3.25,3.2) P12(3.25,4) R2(3.9,-4) R3(3.9,-3.2) R4(3.9,-2.4) R5(3.9,-1.6) R6(3.9,-0.8) R8(3.9,0.8) R9(3.9,1.6) R10(3.9,2.4) R11(3.9,3.2) R12(3.9,4) T1(4.55,-4.8) T2(4.55,-4) T3(4.55,-3.2) T4(4.55,-2.4) T5(4.55,-1.6) T6(4.55,-0.8) T8(4.55,0.8) T9(4.55,1.6) T10(4.55,2.4) T11(4.55,3.2) T12(4.55,4) T13(4.55,4.8) U1(5.2,-4.8) U2(5.2,-4) U3(5.2,-3.2) U4(5.2,-2.4) U5(5.2,-1.6) U6(5.2,-0.8) U8(5.2,0.8) U9(5.2,1.6) U10(5.2,2.4) U11(5.2,3.2) U12(5.2,4) U13(5.2,4.8)
BGA1515-INTEL-SKL_KBL-Y
  round 0.25 smd: A5(-7.541,-8.401) A7(-7.541,-7.946) A9(-7.541,-7.407) A11(-7.541,-6.763) A14(-7.541,-6.119) A16(-7.541,-5.475) A18(-7.541,-4.831) A20(-7.541,-4.187) A22(-7.541,-3.543) A24(-7.541,-2.898) A26(-7.541,-2.254) A28(-7.541,-1.61) A30(-7.541,-0.966) A32(-7.541,-0.322) A34(-7.541,0.322) A36(-7.541,0.966) A38(-7.541,1.61) A40(-7.541,2.255) A42(-7.541,2.899) A44(-7.541,3.543) A46(-7.541,4.187) A48(-7.541,4.831) A50(-7.541,5.475) A52(-7.541,6.119) A54(-7.541,6.764) A56(-7.541,7.408) A58(-7.541,7.953) A60(-7.541,8.401) A62(-7.541,8.856) A64(-7.541,9.31) AA2(-1.932,-9.038) AA4(-1.932,-8.546) AA6(-1.932,-8.053) AA8(-1.932,-7.56) AA10(-1.932,-7.067) AA12(-1.932,-6.575) AA53(-1.932,6.575) AA55(-1.932,7.068) AA57(-1.932,7.56) AB1(-1.61,-9.31) AB3(-1.61,-8.792) AB5(-1.61,-8.299) AB7(-1.61,-7.806) AB9(-1.61,-7.314) AB11(-1.61,-6.821) AB13(-1.605,-6.328) AB54(-1.61,6.821) AB56(-1.61,7.314) AB58(-1.61,7.807) AB64(-1.61,9.31) AC2(-1.288,-9.038) AC4(-1.288,-8.546) AC6(-1.288,-8.053) AC8(-1.288,-7.56) AC10(-1.288,-7.067) AC12(-1.288,-6.575) AC53(-1.288,6.575) AC55(-1.288,7.068) AC57(-1.288,7.56) AD1(-0.966,-9.31) AD3(-0.966,-8.792) AD5(-0.966,-8.299) AD7(-0.966,-7.806) AD9(-0.966,-7.314) AD11(-0.966,-6.821) AD13(-0.961,-6.328) AD54(-0.966,6.821) AD56(-0.966,7.314) AD58(-0.966,7.807) AD64(-0.966,9.31) AE2(-0.644,-9.038) AE4(-0.644,-8.546) AE6(-0.644,-8.053) AE8(-0.644,-7.56) AE10(-0.644,-7.067) AE12(-0.644,-6.575) AE53(-0.644,6.575) AE55(-0.644,7.068) AE57(-0.644,7.56) AF1(-0.322,-9.31) AF3(-0.322,-8.792) AF5(-0.322,-8.299) AF7(-0.322,-7.806) AF9(-0.322,-7.314) AF11(-0.322,-6.821) AF13(-0.317,-6.328) AF54(-0.322,6.821) AF56(-0.322,7.314) AF58(-0.322,7.807) AF60(-0.322,8.299) AF62(-0.322,8.792) AF64(-0.322,9.31) AG2(0,-9.038) AG4(0,-8.546) AG6(0,-8.053) AG8(0,-7.56) AG10(0,-7.067) AG12(0,-6.575) AG53(0,6.575) AG55(0,7.068) AG57(0,7.56) AG59(0,8.053) AG61(0,8.546) AG63(0,9.039) AH1(0.322,-9.31) AH3(0.322,-8.792) AH5(0.322,-8.299) AH7(0.322,-7.806) AH9(0.322,-7.314) AH11(0.322,-6.821) AH13(0.327,-6.328) AH54(0.322,6.821) AH56(0.322,7.314) AH58(0.322,7.807) AH60(0.322,8.299) AH62(0.322,8.792) AH64(0.322,9.31) AJ2(0.644,-9.038) AJ4(0.644,-8.546) AJ6(0.644,-8.053) AJ8(0.644,-7.56) AJ10(0.644,-7.067) AJ12(0.644,-6.575) AJ53(0.644,6.575) AJ55(0.644,7.068) AJ57(0.644,7.56) AJ59(0.644,8.053) AJ61(0.644,8.546) AJ63(0.644,9.039) AK1(0.966,-9.31) AK3(0.966,-8.792) AK5(0.966,-8.299) AK7(0.966,-7.806) AK9(0.966,-7.314) AK11(0.966,-6.821) AK13(0.971,-6.328) AK54(0.966,6.821) AK56(0.966,7.314) AK58(0.966,7.807) AK60(0.966,8.299) AK62(0.966,8.792) AK64(0.966,9.31) AL2(1.288,-9.038) AL4(1.288,-8.546) AL6(1.288,-8.053) AL8(1.288,-7.56) AL10(1.288,-7.067) AL12(1.288,-6.575) AL53(1.288,6.575) AL55(1.288,7.068) AL57(1.288,7.56) AL59(1.288,8.053) AL61(1.288,8.546) AL63(1.288,9.039) AM1(1.61,-9.31) AM3(1.61,-8.792) AM5(1.61,-8.299) AM7(1.61,-7.806) AM9(1.61,-7.314) AM11(1.61,-6.821) AM13(1.615,-6.328) AM54(1.61,6.821) AM56(1.61,7.314) AM58(1.61,7.807) AM60(1.61,8.299) AM62(1.61,8.792) AM64(1.61,9.31) AN2(1.932,-9.038) AN4(1.932,-8.546) AN6(1.932,-8.053) AN8(1.932,-7.56) AN10(1.932,-7.067) AN12(1.932,-6.575) AN53(1.932,6.575) AN55(1.932,7.068) AN57(1.932,7.56) AN59(1.932,8.053) AN61(1.932,8.546) AN63(1.932,9.039) AP1(2.254,-9.31) AP3(2.254,-8.792) AP5(2.254,-8.299) AP7(2.254,-7.806) AP9(2.254,-7.314) AP11(2.254,-6.821) AP13(2.259,-6.328) AP54(2.255,6.821) AP56(2.255,7.314) AP58(2.255,7.807) AP60(2.255,8.299) AP62(2.255,8.792) AP64(2.255,9.31) AR2(2.576,-9.038) AR4(2.576,-8.546) AR6(2.576,-8.053) AR8(2.576,-7.56) AR10(2.576,-7.067) AR12(2.576,-6.575) AR53(2.577,6.575) AR55(2.577,7.068) AR57(2.577,7.56) AR59(2.577,8.053) AR61(2.577,8.546) AR63(2.577,9.039) AT1(2.898,-9.31) AT3(2.898,-8.792) AT5(2.898,-8.299) AT7(2.898,-7.806) AT9(2.898,-7.314) AT11(2.898,-6.821) AT13(2.903,-6.328) AT54(2.898,6.821) AT56(2.898,7.314) AT58(2.898,7.807) AT60(2.898,8.299) AT62(2.898,8.792) AT64(2.898,9.31) AU2(3.22,-9.038) AU4(3.22,-8.546) AU6(3.22,-8.053) AU8(3.22,-7.56) AU10(3.22,-7.067) AU12(3.22,-6.575) AU53(3.221,6.575) AU55(3.221,7.068) AU57(3.221,7.56) AU59(3.221,8.053) AU61(3.221,8.546) AU63(3.221,9.039) AV1(3.543,-9.31) AV3(3.543,-8.792) AV5(3.543,-8.299) AV7(3.543,-7.806) AV9(3.543,-7.314) AV11(3.543,-6.821) AV13(3.543,-6.328) AV15(3.573,-5.881) AV16(3.573,-5.475) AV18(3.573,-4.831) AV20(3.573,-4.187) AV22(3.573,-3.543) AV24(3.573,-2.898) AV26(3.573,-2.254) AV28(3.573,-1.61) AV30(3.573,-0.966) AV32(3.573,-0.322) AV34(3.574,0.322) AV36(3.574,0.966) AV38(3.574,1.61) AV40(3.574,2.255) AV42(3.574,2.898) AV44(3.574,3.543) AV46(3.574,4.187) AV48(3.574,4.831) AV50(3.574,5.475) AV52(3.574,6.119) AV54(3.543,6.821) AV56(3.543,7.314) AV58(3.543,7.807) AV60(3.543,8.299) AV62(3.543,8.792) AV64(3.543,9.31) AW2(3.865,-9.038) AW4(3.865,-8.546) AW6(3.865,-8.053) AW8(3.865,-7.56) AW10(3.865,-7.067) AW12(3.865,-6.575) AW17(3.82,-5.153) AW19(3.82,-4.509) AW21(3.82,-3.865) AW23(3.82,-3.22) AW25(3.82,-2.576) AW27(3.82,-1.932) AW29(3.82,-1.288) AW31(3.82,-0.644) AW33(3.82,0) AW35(3.82,0.644) AW37(3.82,1.288) AW39(3.82,1.932) AW41(3.82,2.577) AW43(3.82,3.221) AW45(3.82,3.865) AW47(3.82,4.509) AW49(3.82,5.153) AW51(3.82,5.797) AW53(3.828,6.441) AW55(3.865,7.068) AW57(3.865,7.56) AW59(3.865,8.053) AW61(3.865,8.546) AW63(3.865,9.039) AY14(3.96,-5.994) AY16(4.066,-5.475) AY18(4.066,-4.831) AY20(4.066,-4.187) AY22(4.066,-3.543) AY24(4.066,-2.898) AY26(4.066,-2.254) AY28(4.066,-1.61) AY30(4.066,-0.966) AY32(4.066,-0.322) AY34(4.066,0.322) AY36(4.066,0.966) AY38(4.066,1.61) AY40(4.066,2.255) AY42(4.066,2.898) AY44(4.066,3.543) AY46(4.066,4.187) AY48(4.066,4.831) AY50(4.066,5.475) AY52(4.066,6.119) B3(-7.112,-8.881) B4(-7.112,-8.452) B6(-7.112,-8.022) B8(-7.112,-7.593) B10(-7.269,-7.085) B12(-7.269,-6.441) B15(-7.269,-5.797) B17(-7.269,-5.153) B19(-7.269,-4.509) B21(-7.269,-3.865) B23(-7.269,-3.22) B25(-7.269,-2.576) B27(-7.269,-1.932) B29(-7.269,-1.288) B31(-7.269,-0.644) B33(-7.269,0) B35(-7.269,0.644) B37(-7.269,1.288) B39(-7.269,1.932) B41(-7.269,2.577) B43(-7.269,3.221) B45(-7.269,3.865) B47(-7.269,4.509) B49(-7.269,5.153) B51(-7.269,5.797) B53(-7.269,6.441) B55(-7.269,7.086) B58(-7.178,7.777) B61(-7.111,8.48) B62(-7.111,8.881) B64(-7.086,9.31) BA1(4.187,-9.31) BA3(4.187,-8.792) BA5(4.187,-8.299) BA7(4.187,-7.806) BA9(4.187,-7.314) BA11(4.187,-6.821) BA13(4.187,-6.328) BA15(4.312,-5.797) BA17(4.312,-5.153) BA19(4.312,-4.509) BA21(4.312,-3.865) BA23(4.312,-3.22) BA25(4.312,-2.576) BA27(4.312,-1.932) BA29(4.312,-1.288) BA31(4.312,-0.644) BA33(4.313,0) BA35(4.313,0.644) BA37(4.313,1.288) BA39(4.313,1.932) BA41(4.313,2.577) BA43(4.313,3.221) BA45(4.313,3.865) BA47(4.313,4.509) BA49(4.313,5.153) BA51(4.313,5.797) BA53(4.32,6.441) BA56(4.187,7.314) BA58(4.187,7.807) BA60(4.187,8.299) BA62(4.187,8.792) BA64(4.187,9.31) BB2(4.509,-9.038) BB4(4.509,-8.546) BB6(4.509,-8.053) BB8(4.509,-7.56) BB10(4.509,-7.067) BB12(4.559,-6.548) BB14(4.559,-6.119) BB16(4.559,-5.475) BB18(4.559,-4.831) BB20(4.559,-4.187) BB22(4.559,-3.543) BB24(4.559,-2.898) BB26(4.559,-2.254) BB28(4.559,-1.61) BB30(4.559,-0.966) BB32(4.559,-0.322) BB34(4.559,0.322) BB36(4.559,0.966) BB38(4.559,1.61) BB40(4.559,2.255) BB42(4.559,2.898) BB44(4.559,3.543) BB46(4.559,4.187) BB48(4.559,4.831) BB50(4.559,5.475) BB52(4.559,6.119) BB54(4.559,6.764) BB57(4.509,7.56) BB59(4.509,8.053) BB61(4.509,8.546) BB63(4.509,9.039) BC1(4.831,-9.31) BC3(4.831,-8.792) BC5(4.831,-8.299) BC7(4.831,-7.806) BC9(4.831,-7.314) BC11(4.978,-6.695) BC15(4.805,-5.797) BC17(4.805,-5.153) BC19(4.805,-4.509) BC21(4.805,-3.865) BC23(4.805,-3.22) BC25(4.805,-2.576) BC27(4.805,-1.932) BC29(4.805,-1.288) BC31(4.805,-0.644) BC33(4.805,0) BC35(4.805,0.644) BC37(4.805,1.288) BC39(4.805,1.932) BC41(4.805,2.577) BC43(4.805,3.221) BC45(4.805,3.865) BC47(4.805,4.509) BC49(4.805,5.153) BC51(4.805,5.797) BC53(4.805,6.441) BC55(4.805,7.086) BC58(4.831,7.807) BC60(4.831,8.299) BC62(4.831,8.792) BC64(4.831,9.31) BD2(5.153,-9.038) BD4(5.153,-8.546) BD6(5.153,-8.053) BD8(5.153,-7.56) BD10(5.148,-7.067) BD14(5.052,-6.119) BD16(5.052,-5.475) BD18(5.052,-4.831) BD20(5.052,-4.187) BD22(5.052,-3.543) BD24(5.052,-2.898) BD26(5.052,-2.254) BD28(5.052,-1.61) BD30(5.052,-0.966) BD32(5.052,-0.322) BD34(5.052,0.322) BD36(5.052,0.966) BD38(5.052,1.61) BD40(5.052,2.255) BD42(5.052,2.898) BD44(5.052,3.543) BD46(5.052,4.187) BD48(5.052,4.831) BD50(5.052,5.475) BD52(5.052,6.119) BD54(5.052,6.764) BD56(5.052,7.408) BD59(5.237,8.133) BD61(5.153,8.546) BD63(5.153,9.039) BE12(5.298,-6.441) BE15(5.298,-5.797) BE17(5.298,-5.153) BE19(5.298,-4.509) BE21(5.298,-3.865) BE23(5.298,-3.22) BE25(5.298,-2.576) BE27(5.298,-1.932) BE29(5.298,-1.288) BE31(5.298,-0.644) BE33(5.298,0) BE35(5.298,0.644) BE37(5.298,1.288) BE39(5.298,1.932) BE41(5.298,2.577) BE43(5.298,3.221) BE45(5.298,3.865) BE47(5.298,4.509) BE49(5.298,5.153) BE51(5.298,5.797) BE53(5.298,6.441) BE55(5.298,7.086) BE57(5.298,7.729) BF1(5.475,-9.31) BF3(5.475,-8.792) BF5(5.475,-8.299) BF7(5.475,-7.806) BF9(5.48,-7.309) BF11(5.544,-6.763) BF14(5.544,-6.119) BF16(5.544,-5.475) BF18(5.544,-4.831) BF20(5.544,-4.187) BF22(5.544,-3.543) BF24(5.544,-2.898) BF26(5.544,-2.254) BF28(5.544,-1.61) BF30(5.544,-0.966) BF32(5.544,-0.322) BF34(5.545,0.322) BF36(5.545,0.966) BF38(5.545,1.61) BF40(5.545,2.255) BF42(5.545,2.898) BF44(5.545,3.543) BF46(5.545,4.187) BF48(5.545,4.831) BF50(5.545,5.475) BF52(5.545,6.119) BF54(5.545,6.764) BF56(5.545,7.408) BF59(5.639,8.164) BF62(5.475,8.792) BF64(5.475,9.31) BG2(5.797,-9.038) BG4(5.797,-8.546) BG6(5.797,-8.053) BG8(5.797,-7.56) BG10(5.89,-7.17) BG12(5.791,-6.441) BG15(5.791,-5.797) BG17(5.791,-5.153) BG19(5.791,-4.509) BG21(5.791,-3.865) BG23(5.791,-3.22) BG25(5.791,-2.576) BG27(5.791,-1.932) BG29(5.791,-1.288) BG31(5.791,-0.644) BG33(5.791,0) BG35(5.791,0.644) BG37(5.791,1.288) BG39(5.791,1.932) BG41(5.791,2.577) BG43(5.791,3.221) BG45(5.791,3.865) BG47(5.791,4.509) BG49(5.791,5.153) BG51(5.791,5.797) BG53(5.791,6.441) BG55(5.791,7.086) BG57(5.791,7.729) BG61(5.797,8.546) BG63(5.797,9.039) BH11(6.037,-6.763) BH14(6.037,-6.119) BH16(6.037,-5.475) BH18(6.037,-4.831) BH20(6.037,-4.187) BH22(6.037,-3.543) BH24(6.037,-2.898) BH26(6.037,-2.254) BH28(6.037,-1.61) BH30(6.037,-0.966) BH32(6.037,-0.322) BH34(6.037,0.322) BH36(6.037,0.966) BH38(6.037,1.61) BH40(6.037,2.255) BH42(6.037,2.898) BH44(6.037,3.543) BH46(6.037,4.187) BH48(6.037,4.831) BH50(6.037,5.475) BH52(6.037,6.119) BH54(6.037,6.764) BH56(6.037,7.408) BH59(6.037,8.052) BJ1(6.177,-9.31) BJ3(6.253,-8.881) BJ4(6.253,-8.452) BJ6(6.253,-8.022) BJ8(6.253,-7.593) BJ10(6.283,-7.085) BJ12(6.283,-6.441) BJ15(6.283,-5.797) BJ17(6.283,-5.153) BJ19(6.283,-4.509) BJ21(6.283,-3.865) BJ23(6.283,-3.22) BJ25(6.283,-2.576) BJ27(6.283,-1.932) BJ29(6.283,-1.288) BJ31(6.283,-0.644) BJ33(6.284,0) BJ35(6.284,0.644) BJ37(6.284,1.288) BJ39(6.284,1.932) BJ41(6.284,2.577) BJ43(6.284,3.221) BJ45(6.284,3.865) BJ47(6.284,4.509) BJ49(6.284,5.153) BJ51(6.284,5.797) BJ53(6.284,6.441) BJ55(6.284,7.086) BJ57(6.284,7.729) BJ61(6.253,8.452) BJ62(6.253,8.881) BJ64(6.177,9.31) BK11(6.53,-6.763) BK14(6.53,-6.119) BK16(6.53,-5.475) BK18(6.53,-4.831) BK20(6.53,-4.187) BK22(6.53,-3.543) BK24(6.53,-2.898) BK26(6.53,-2.254) BK28(6.53,-1.61) BK30(6.53,-0.966) BK32(6.53,-0.322) BK34(6.53,0.322) BK36(6.53,0.966) BK38(6.53,1.61) BK40(6.53,2.255) BK42(6.53,2.898) BK44(6.53,3.543) BK46(6.53,4.187) BK48(6.53,4.831) BK50(6.53,5.475) BK52(6.53,6.119) BK54(6.53,6.764) BK56(6.53,7.408) BK59(6.454,8.103) BL1(6.631,-9.31) BL3(6.682,-8.881) BL4(6.682,-8.452) BL6(6.682,-8.022) BL8(6.682,-7.593) BL10(6.776,-7.085) BL12(6.776,-6.441) BL15(6.776,-5.797) BL17(6.776,-5.153) BL19(6.776,-4.509) BL21(6.776,-3.865) BL23(6.776,-3.22) BL25(6.776,-2.576) BL27(6.776,-1.932) BL29(6.776,-1.288) BL31(6.776,-0.644) BL33(6.776,0) BL35(6.776,0.644) BL37(6.776,1.288) BL39(6.776,1.932) BL41(6.776,2.577) BL43(6.776,3.221) BL45(6.776,3.865) BL47(6.776,4.509) BL49(6.776,5.153) BL51(6.776,5.797) BL53(6.776,6.441) BL55(6.776,7.086) BL57(6.769,7.729) BL61(6.682,8.452) BL62(6.682,8.881) BL64(6.632,9.31) BM11(7.023,-6.763) BM14(7.023,-6.119) BM16(7.023,-5.475) BM18(7.023,-4.831) BM20(7.023,-4.187) BM22(7.023,-3.543) BM24(7.023,-2.898) BM26(7.023,-2.254) BM28(7.023,-1.61) BM30(7.023,-0.966) BM32(7.023,-0.322) BM34(7.023,0.322) BM36(7.023,0.966) BM38(7.023,1.61) BM40(7.023,2.255) BM42(7.023,2.898) BM44(7.023,3.543) BM46(7.023,4.187) BM48(7.023,4.831) BM50(7.023,5.475) BM52(7.023,6.119) BM54(7.023,6.764) BM56(7.023,7.408) BM59(6.923,8.099) BN1(7.086,-9.31) BN3(7.111,-8.881) BN4(7.111,-8.452) BN6(7.111,-8.022) BN8(7.111,-7.593) BN10(7.269,-7.085) BN12(7.269,-6.441) BN15(7.269,-5.797) BN17(7.269,-5.153) BN19(7.269,-4.509) BN21(7.269,-3.865) BN23(7.269,-3.22) BN25(7.269,-2.576) BN27(7.269,-1.932) BN29(7.269,-1.288) BN31(7.269,-0.644) BN33(7.269,0) BN35(7.269,0.644) BN37(7.269,1.288) BN39(7.269,1.932) BN41(7.269,2.577) BN43(7.269,3.221) BN45(7.269,3.865) BN47(7.269,4.509) BN49(7.269,5.153) BN51(7.269,5.797) BN53(7.269,6.441) BN55(7.269,7.086) BN58(7.178,7.777) BN61(7.112,8.452) BN62(7.112,8.881) BN64(7.086,9.31) BP1(7.541,-9.31) BP3(7.541,-8.855) BP5(7.541,-8.401) BP7(7.541,-7.946) BP9(7.541,-7.407) BP11(7.541,-6.763) BP14(7.541,-6.119) BP16(7.541,-5.475) BP18(7.541,-4.831) BP20(7.541,-4.187) BP22(7.541,-3.543) BP24(7.541,-2.898) BP26(7.541,-2.254) BP28(7.541,-1.61) BP30(7.541,-0.966) BP32(7.541,-0.322) BP34(7.541,0.322) BP36(7.541,0.966) BP38(7.541,1.61) BP40(7.541,2.255) BP42(7.541,2.898) BP44(7.541,3.543) BP46(7.541,4.187) BP48(7.541,4.831) BP50(7.541,5.475) BP52(7.541,6.119) BP54(7.541,6.764) BP56(7.541,7.408) BP58(7.541,7.946) BP60(7.541,8.401) BP62(7.541,8.856) BP64(7.541,9.31) C11(-7.023,-6.763) C14(-7.023,-6.119) C16(-7.023,-5.475) C18(-7.023,-4.831) C20(-7.023,-4.187) C22(-7.023,-3.543) C24(-7.023,-2.898) C26(-7.023,-2.254) C28(-7.023,-1.61) C30(-7.023,-0.966) C32(-7.023,-0.322) C34(-7.023,0.322) C36(-7.023,0.966) C38(-7.023,1.61) C40(-7.023,2.255) C42(-7.023,2.899) C44(-7.023,3.543) C46(-7.023,4.187) C48(-7.023,4.831) C50(-7.023,5.475) C52(-7.023,6.119) C54(-7.023,6.764) C56(-7.023,7.403) C59(-6.918,8.11) D1(-6.632,-9.31) D3(-6.682,-8.881) D4(-6.682,-8.452) D6(-6.682,-8.022) D8(-6.682,-7.593) D10(-6.776,-7.085) D12(-6.776,-6.441) D15(-6.776,-5.797) D17(-6.776,-5.153) D19(-6.776,-4.509) D21(-6.776,-3.865) D23(-6.776,-3.22) D25(-6.776,-2.576) D27(-6.776,-1.932) D29(-6.776,-1.288) D31(-6.776,-0.644) D33(-6.776,0) D35(-6.776,0.644) D37(-6.776,1.288) D39(-6.776,1.932) D41(-6.776,2.577) D43(-6.776,3.221) D45(-6.776,3.865) D47(-6.776,4.509) D49(-6.776,5.153) D51(-6.776,5.797) D53(-6.776,6.441) D55(-6.687,7.149) D57(-6.756,7.725) D61(-6.682,8.452) D62(-6.682,8.881) D64(-6.631,9.31) E11(-6.53,-6.763) E14(-6.53,-6.119) E16(-6.53,-5.475) E18(-6.53,-4.831) E20(-6.53,-4.187) E22(-6.53,-3.543) E24(-6.53,-2.898) E26(-6.53,-2.254) E28(-6.53,-1.61) E30(-6.53,-0.966) E32(-6.53,-0.322) E34(-6.53,0.322) E36(-6.53,0.966) E38(-6.53,1.61) E40(-6.53,2.255) E42(-6.53,2.899) E44(-6.53,3.543) E46(-6.53,4.187) E48(-6.53,4.831) E50(-6.53,5.475) E52(-6.53,6.119) E54(-6.53,6.764) E56(-6.403,7.509) E59(-6.413,8.089) F1(-6.177,-9.31) F3(-6.253,-8.881) F4(-6.253,-8.452) F6(-6.253,-8.022) F8(-6.253,-7.593) F10(-6.284,-7.085) F12(-6.284,-6.441) F15(-6.284,-5.797) F17(-6.284,-5.153) F19(-6.284,-4.509) F21(-6.284,-3.865) F23(-6.284,-3.22) F25(-6.284,-2.576) F27(-6.284,-1.932) F29(-6.284,-1.288) F31(-6.284,-0.644) F33(-6.283,0) F35(-6.283,0.644) F37(-6.283,1.288) F39(-6.283,1.932) F41(-6.283,2.577) F43(-6.283,3.221) F45(-6.283,3.865) F47(-6.283,4.509) F49(-6.283,5.153) F51(-6.283,5.797) F53(-6.283,6.441) F55(-6.283,7.086) F61(-6.253,8.477) F62(-6.253,8.881) F64(-6.171,9.31) G11(-6.037,-6.763) G14(-6.037,-6.119) G16(-6.037,-5.475) G18(-6.037,-4.831) G20(-6.037,-4.187) G22(-6.037,-3.543) G24(-6.037,-2.898) G26(-6.037,-2.254) G28(-6.037,-1.61) G30(-6.037,-0.966) G32(-6.037,-0.322) G34(-6.037,0.322) G36(-6.037,0.966) G38(-6.037,1.61) G40(-6.037,2.255) G42(-6.037,2.899) G44(-6.037,3.543) G46(-6.037,4.187) G48(-6.037,4.831) G50(-6.037,5.475) G52(-6.037,6.119) G54(-6.037,6.764) G56(-6.01,7.418) G58(-6.095,7.819) H2(-5.797,-9.038) H4(-5.797,-8.546) H6(-5.797,-8.053) H8(-5.797,-7.56) H10(-5.89,-7.17) H12(-5.791,-6.441) H15(-5.791,-5.797) H17(-5.791,-5.153) H19(-5.791,-4.509) H21(-5.791,-3.865) H23(-5.791,-3.22) H25(-5.791,-2.576) H27(-5.791,-1.932) H29(-5.791,-1.288) H31(-5.791,-0.644) H33(-5.791,0) H35(-5.791,0.644) H37(-5.791,1.288) H39(-5.791,1.932) H41(-5.791,2.577) H43(-5.791,3.221) H45(-5.791,3.865) H47(-5.791,4.509) H49(-5.791,5.153) H51(-5.791,5.797) H53(-5.791,6.441) H55(-5.783,7.086) H59(-5.839,8.131) H61(-5.797,8.546) J1(-5.475,-9.31) J3(-5.475,-8.792) J5(-5.475,-8.299) J7(-5.475,-7.806) J9(-5.475,-7.314) J11(-5.545,-6.763) J14(-5.545,-6.119) J16(-5.545,-5.475) J18(-5.545,-4.831) J20(-5.545,-4.187) J22(-5.545,-3.543) J24(-5.545,-2.898) J26(-5.545,-2.254) J28(-5.545,-1.61) J30(-5.545,-0.966) J32(-5.545,-0.322) J34(-5.544,0.322) J36(-5.544,0.966) J38(-5.544,1.61) J40(-5.544,2.255) J42(-5.544,2.899) J44(-5.544,3.543) J46(-5.544,4.187) J48(-5.544,4.831) J50(-5.544,5.475) J52(-5.544,6.119) J54(-5.544,6.764) J56(-5.544,7.408) J58(-5.605,7.806) J60(-5.475,8.299) J62(-5.475,8.792) J64(-5.475,9.31) K12(-5.298,-6.441) K15(-5.298,-5.797) K17(-5.298,-5.153) K19(-5.298,-4.509) K21(-5.298,-3.865) K23(-5.298,-3.22) K25(-5.298,-2.576) K27(-5.298,-1.932) K29(-5.298,-1.288) K31(-5.298,-0.644) K33(-5.298,0) K35(-5.298,0.644) K37(-5.298,1.288) K39(-5.298,1.932) K41(-5.298,2.577) K43(-5.298,3.221) K45(-5.298,3.865) K47(-5.298,4.509) K49(-5.298,5.153) K51(-5.298,5.797) K53(-5.298,6.441) K55(-5.298,7.086) L2(-5.153,-9.038) L4(-5.153,-8.546) L6(-5.153,-8.053) L8(-5.153,-7.56) L10(-5.153,-7.067) L14(-5.052,-6.119) L16(-5.052,-5.475) L18(-5.052,-4.831) L20(-5.052,-4.187) L22(-5.052,-3.543) L24(-5.052,-2.898) L26(-5.052,-2.254) L28(-5.052,-1.61) L30(-5.052,-0.966) L32(-5.052,-0.322) L34(-5.052,0.322) L36(-5.052,0.966) L38(-5.052,1.61) L40(-5.052,2.255) L42(-5.052,2.899) L44(-5.052,3.543) L46(-5.052,4.187) L48(-5.052,4.831) L50(-5.052,5.475) L52(-5.052,6.119) L54(-5.052,6.764) L57(-5.232,7.661) L59(-5.153,8.053) L61(-5.153,8.546) M1(-4.831,-9.31) M3(-4.831,-8.792) M5(-4.831,-8.299) M7(-4.831,-7.806) M9(-4.831,-7.314) M11(-4.831,-6.821) M15(-4.805,-5.797) M17(-4.805,-5.153) M19(-4.805,-4.509) M21(-4.805,-3.865) M23(-4.805,-3.22) M25(-4.805,-2.576) M27(-4.805,-1.932) M29(-4.805,-1.288) M31(-4.805,-0.644) M33(-4.805,0) M35(-4.805,0.644) M37(-4.805,1.288) M39(-4.805,1.932) M41(-4.805,2.577) M43(-4.805,3.221) M45(-4.805,3.865) M47(-4.805,4.509) M49(-4.805,5.153) M51(-4.805,5.797) M53(-4.805,6.441) M56(-4.99,7.342) M58(-4.831,7.807) M64(-4.831,9.31) N2(-4.509,-9.038) N4(-4.509,-8.546) N6(-4.509,-8.053) N8(-4.509,-7.56) N10(-4.509,-7.067) N12(-4.509,-6.575) N14(-4.559,-6.119) N16(-4.559,-5.475) N18(-4.559,-4.831) N20(-4.559,-4.187) N22(-4.559,-3.543) N24(-4.559,-2.898) N26(-4.559,-2.254) N28(-4.559,-1.61) N30(-4.559,-0.966) N32(-4.559,-0.322) N34(-4.559,0.322) N36(-4.559,0.966) N38(-4.559,1.61) N40(-4.559,2.255) N42(-4.559,2.899) N44(-4.559,3.543) N46(-4.559,4.187) N48(-4.559,4.831) N50(-4.559,5.475) N52(-4.559,6.119) N54(-4.587,6.777) N55(-4.625,7.177) N57(-4.509,7.56) P1(-4.187,-9.31) P3(-4.187,-8.792) P5(-4.187,-8.299) P7(-4.187,-7.806) P9(-4.187,-7.314) P11(-4.187,-6.821) P13(-4.182,-6.328) P52(-4.277,6.424) P54(-4.187,6.821) P56(-4.187,7.314) P58(-4.187,7.807) P64(-4.187,9.31) R2(-3.865,-9.038) R4(-3.865,-8.546) R6(-3.865,-8.053) R8(-3.865,-7.56) R10(-3.865,-7.067) R12(-3.865,-6.575) R53(-3.865,6.575) R55(-3.865,7.068) R57(-3.865,7.56) T1(-3.543,-9.31) T3(-3.543,-8.792) T5(-3.543,-8.299) T7(-3.543,-7.806) T9(-3.543,-7.314) T11(-3.543,-6.821) T13(-3.538,-6.328) T54(-3.543,6.821) T56(-3.543,7.314) T58(-3.543,7.807) T64(-3.543,9.31) U2(-3.221,-9.038) U4(-3.221,-8.546) U6(-3.221,-8.053) U8(-3.221,-7.56) U10(-3.221,-7.067) U12(-3.221,-6.575) U53(-3.22,6.575) U55(-3.22,7.068) U57(-3.22,7.56) V1(-2.898,-9.31) V3(-2.898,-8.792) V5(-2.898,-8.299) V7(-2.898,-7.806) V9(-2.898,-7.314) V11(-2.898,-6.821) V13(-2.894,-6.328) V54(-2.898,6.821) V56(-2.898,7.314) V58(-2.898,7.807) V64(-2.898,9.31) W2(-2.577,-9.038) W4(-2.577,-8.546) W6(-2.577,-8.053) W8(-2.577,-7.56) W10(-2.577,-7.067) W12(-2.577,-6.575) W53(-2.576,6.575) W55(-2.576,7.068) W57(-2.576,7.56) Y1(-2.255,-9.31) Y3(-2.255,-8.792) Y5(-2.255,-8.299) Y7(-2.255,-7.806) Y9(-2.255,-7.314) Y11(-2.255,-6.821) Y13(-2.249,-6.328) Y54(-2.254,6.821) Y56(-2.254,7.314) Y58(-2.254,7.807) Y64(-2.254,9.31)
  round 0.28 smd: AA15(-1.87,-5.846) AA51(-1.87,6.041) AC15(-1.311,-5.846) AC51(-1.311,6.041) AE15(-0.752,-5.846) AE51(-0.752,6.041) AF15(-0.193,-5.846) AF51(-0.193,6.041) AH15(0.366,-5.846) AH51(0.366,6.041) AK15(0.924,-5.846) AK51(0.924,6.041) AL15(1.483,-5.846) AL51(1.483,6.041) AN15(2.042,-5.846) AN51(2.042,6.041) AR15(2.601,-5.846) AR51(2.601,6.041) AT15(3.16,-5.846) AT16(3.16,-5.351) AT18(3.16,-4.855) AT19(3.16,-4.36) AT21(3.16,-3.865) AT23(3.16,-3.37) AT24(3.16,-2.874) AT26(3.16,-2.379) AT27(3.16,-1.884) AT29(3.16,-1.388) AT30(3.16,-0.893) AT32(3.16,-0.398) AT33(3.16,0.098) AT35(3.16,0.593) AT36(3.16,1.088) AT38(3.16,1.583) AT40(3.16,2.079) AT41(3.16,2.574) AT43(3.16,3.069) AT44(3.16,3.565) AT46(3.16,4.06) AT47(3.16,4.555) AT49(3.16,5.051) AT50(3.16,5.546) AT51(3.16,6.041) R15(-4.105,-5.846) R16(-4.105,-5.351) R18(-4.105,-4.855) R19(-4.105,-4.36) R21(-4.105,-3.865) R23(-4.105,-3.37) R24(-4.105,-2.874) R26(-4.105,-2.379) R27(-4.105,-1.884) R29(-4.105,-1.388) R30(-4.105,-0.893) R32(-4.105,-0.398) R33(-4.105,0.098) R35(-4.105,0.593) R36(-4.105,1.088) R38(-4.105,1.583) R40(-4.105,2.079) R41(-4.105,2.574) R43(-4.105,3.069) R44(-4.105,3.565) R46(-4.105,4.06) R47(-4.105,4.555) R49(-4.105,5.051) R50(-4.105,5.546) R51(-4.105,6.041) T15(-3.546,-5.846) T51(-3.546,6.041) V15(-2.987,-5.846) V51(-2.987,6.041) Y15(-2.428,-5.846) Y51(-2.428,6.041)
  round 0.381 smd: AA16(-1.87,-5.351) AA18(-1.87,-4.855) AA19(-1.87,-4.36) AA21(-1.87,-3.865) AA23(-1.87,-3.37) AA24(-1.87,-2.874) AA26(-1.87,-2.379) AA27(-1.87,-1.884) AA29(-1.87,-1.388) AA30(-1.87,-0.893) AA32(-1.87,-0.398) AA33(-1.87,0.098) AA35(-1.87,0.593) AA36(-1.87,1.088) AA38(-1.87,1.583) AA40(-1.87,2.079) AA41(-1.87,2.574) AA43(-1.87,3.069) AA44(-1.87,3.565) AA46(-1.87,4.06) AA47(-1.87,4.555) AA49(-1.87,5.051) AA50(-1.87,5.546) AC16(-1.311,-5.351) AC18(-1.311,-4.855) AC19(-1.311,-4.36) AC21(-1.311,-3.865) AC23(-1.311,-3.37) AC24(-1.311,-2.874) AC26(-1.311,-2.379) AC27(-1.311,-1.884) AC29(-1.311,-1.388) AC30(-1.311,-0.893) AC32(-1.311,-0.398) AC33(-1.311,0.098) AC35(-1.311,0.593) AC36(-1.311,1.088) AC38(-1.311,1.583) AC40(-1.311,2.079) AC41(-1.311,2.574) AC43(-1.311,3.069) AC44(-1.311,3.565) AC46(-1.311,4.06) AC47(-1.311,4.555) AC49(-1.311,5.051) AC50(-1.311,5.546) AE16(-0.752,-5.351) AE18(-0.752,-4.855) AE19(-0.752,-4.36) AE21(-0.752,-3.865) AE23(-0.752,-3.37) AE24(-0.752,-2.874) AE26(-0.752,-2.379) AE27(-0.752,-1.884) AE29(-0.752,-1.388) AE30(-0.752,-0.893) AE32(-0.752,-0.398) AE33(-0.752,0.098) AE35(-0.752,0.593) AE36(-0.752,1.088) AE38(-0.752,1.583) AE40(-0.752,2.079) AE41(-0.752,2.574) AE43(-0.752,3.069) AE44(-0.752,3.565) AE46(-0.752,4.06) AE47(-0.752,4.555) AE49(-0.752,5.051) AE50(-0.752,5.546) AF16(-0.193,-5.351) AF18(-0.193,-4.855) AF19(-0.193,-4.36) AF21(-0.193,-3.865) AF23(-0.193,-3.37) AF24(-0.193,-2.874) AF26(-0.193,-2.379) AF27(-0.193,-1.884) AF29(-0.193,-1.388) AF30(-0.193,-0.893) AF32(-0.193,-0.398) AF33(-0.193,0.098) AF35(-0.193,0.593) AF36(-0.193,1.088) AF38(-0.193,1.583) AF40(-0.193,2.079) AF41(-0.193,2.574) AF43(-0.193,3.069) AF44(-0.193,3.565) AF46(-0.193,4.06) AF47(-0.193,4.555) AF49(-0.193,5.051) AF50(-0.193,5.546) AH16(0.366,-5.351) AH18(0.366,-4.855) AH19(0.366,-4.36) AH21(0.366,-3.865) AH23(0.366,-3.37) AH24(0.366,-2.874) AH26(0.366,-2.379) AH27(0.366,-1.884) AH29(0.366,-1.388) AH30(0.366,-0.893) AH32(0.366,-0.398) AH33(0.366,0.098) AH35(0.366,0.593) AH36(0.366,1.088) AH38(0.366,1.583) AH40(0.366,2.079) AH41(0.366,2.574) AH43(0.366,3.069) AH44(0.366,3.565) AH46(0.366,4.06) AH47(0.366,4.555) AH49(0.366,5.051) AH50(0.366,5.546) AK16(0.924,-5.351) AK18(0.924,-4.855) AK19(0.924,-4.36) AK21(0.924,-3.865) AK23(0.924,-3.37) AK24(0.924,-2.874) AK26(0.924,-2.379) AK27(0.924,-1.884) AK29(0.924,-1.388) AK30(0.924,-0.893) AK32(0.924,-0.398) AK33(0.924,0.098) AK35(0.924,0.593) AK36(0.924,1.088) AK38(0.924,1.583) AK40(0.924,2.079) AK41(0.924,2.574) AK43(0.924,3.069) AK44(0.924,3.565) AK46(0.924,4.06) AK47(0.924,4.555) AK49(0.924,5.051) AK50(0.924,5.546) AL16(1.483,-5.351) AL18(1.483,-4.855) AL19(1.483,-4.36) AL21(1.483,-3.865) AL23(1.483,-3.37) AL24(1.483,-2.874) AL26(1.483,-2.379) AL27(1.483,-1.884) AL29(1.483,-1.388) AL30(1.483,-0.893) AL32(1.483,-0.398) AL33(1.483,0.098) AL35(1.483,0.593) AL36(1.483,1.088) AL38(1.483,1.583) AL40(1.483,2.079) AL41(1.483,2.574) AL43(1.483,3.069) AL44(1.483,3.565) AL46(1.483,4.06) AL47(1.483,4.555) AL49(1.483,5.051) AL50(1.483,5.546) AN16(2.042,-5.351) AN18(2.042,-4.855) AN19(2.042,-4.36) AN21(2.042,-3.865) AN23(2.042,-3.37) AN24(2.042,-2.874) AN26(2.042,-2.379) AN27(2.042,-1.884) AN29(2.042,-1.388) AN30(2.042,-0.893) AN32(2.042,-0.398) AN33(2.042,0.098) AN35(2.042,0.593) AN36(2.042,1.088) AN38(2.042,1.583) AN40(2.042,2.079) AN41(2.042,2.574) AN43(2.042,3.069) AN44(2.042,3.565) AN46(2.042,4.06) AN47(2.042,4.555) AN49(2.042,5.051) AN50(2.042,5.546) AR16(2.601,-5.351) AR18(2.601,-4.855) AR19(2.601,-4.36) AR21(2.601,-3.865) AR23(2.601,-3.37) AR24(2.601,-2.874) AR26(2.601,-2.379) AR27(2.601,-1.884) AR29(2.601,-1.388) AR30(2.601,-0.893) AR32(2.601,-0.398) AR33(2.601,0.098) AR35(2.601,0.593) AR36(2.601,1.088) AR38(2.601,1.583) AR40(2.601,2.079) AR41(2.601,2.574) AR43(2.601,3.069) AR44(2.601,3.565) AR46(2.601,4.06) AR47(2.601,4.555) AR49(2.601,5.051) AR50(2.601,5.546) T16(-3.546,-5.351) T18(-3.546,-4.855) T19(-3.546,-4.36) T21(-3.546,-3.865) T23(-3.546,-3.37) T24(-3.546,-2.874) T26(-3.546,-2.379) T27(-3.546,-1.884) T29(-3.546,-1.388) T30(-3.546,-0.893) T32(-3.546,-0.398) T33(-3.546,0.098) T35(-3.546,0.593) T36(-3.546,1.088) T38(-3.546,1.583) T40(-3.546,2.079) T41(-3.546,2.574) T43(-3.546,3.069) T44(-3.546,3.565) T46(-3.546,4.06) T47(-3.546,4.555) T49(-3.546,5.051) T50(-3.546,5.546) V16(-2.987,-5.351) V18(-2.987,-4.855) V19(-2.987,-4.36) V21(-2.987,-3.865) V23(-2.987,-3.37) V24(-2.987,-2.874) V26(-2.987,-2.379) V27(-2.987,-1.884) V29(-2.987,-1.388) V30(-2.987,-0.893) V32(-2.987,-0.398) V33(-2.987,0.098) V35(-2.987,0.593) V36(-2.987,1.088) V38(-2.987,1.583) V40(-2.987,2.079) V41(-2.987,2.574) V43(-2.987,3.069) V44(-2.987,3.565) V46(-2.987,4.06) V47(-2.987,4.555) V49(-2.987,5.051) V50(-2.987,5.546) Y16(-2.428,-5.351) Y18(-2.428,-4.855) Y19(-2.428,-4.36) Y21(-2.428,-3.865) Y23(-2.428,-3.37) Y24(-2.428,-2.874) Y26(-2.428,-2.379) Y27(-2.428,-1.884) Y29(-2.428,-1.388) Y30(-2.428,-0.893) Y32(-2.428,-0.398) Y33(-2.428,0.098) Y35(-2.428,0.593) Y36(-2.428,1.088) Y38(-2.428,1.583) Y40(-2.428,2.079) Y41(-2.428,2.574) Y43(-2.428,3.069) Y44(-2.428,3.565) Y46(-2.428,4.06) Y47(-2.428,4.555) Y49(-2.428,5.051) Y50(-2.428,5.546)
  round 0.325 smd: AA59(-1.932,8.053) AA61(-1.932,8.546) AA63(-1.932,9.039) AB60(-1.61,8.299) AB62(-1.61,8.792) AC59(-1.288,8.053) AC61(-1.288,8.546) AC63(-1.288,9.039) AD60(-0.966,8.299) AD62(-0.966,8.792) AE59(-0.644,8.053) AE61(-0.644,8.546) AE63(-0.644,9.039) H63(-5.797,9.039) L63(-5.153,9.039) M60(-4.831,8.299) M62(-4.831,8.792) N59(-4.509,8.053) N61(-4.509,8.546) N63(-4.509,9.039) P60(-4.187,8.299) P62(-4.187,8.792) R59(-3.865,8.053) R61(-3.865,8.546) R63(-3.865,9.039) T60(-3.543,8.299) T62(-3.543,8.792) U59(-3.22,8.053) U61(-3.22,8.546) U63(-3.22,9.039) V60(-2.898,8.299) V62(-2.898,8.792) W59(-2.576,8.053) W61(-2.576,8.546) W63(-2.576,9.039) Y60(-2.254,8.299) Y62(-2.254,8.792)
